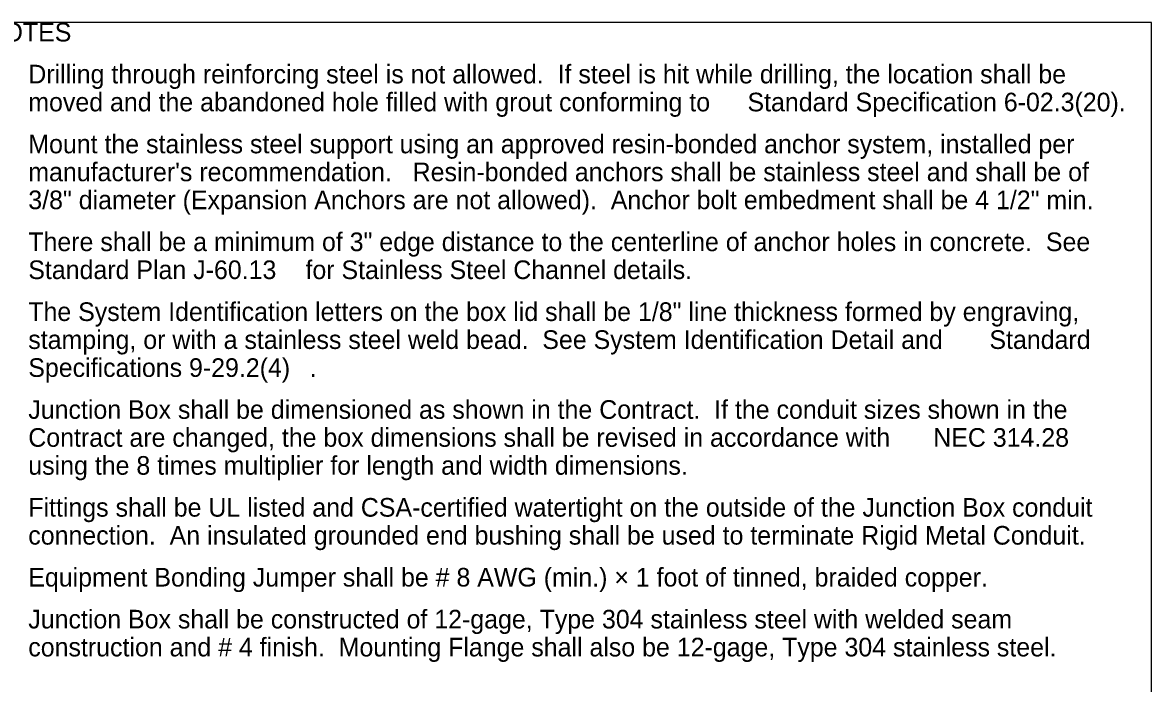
# Model space of a CAD drawing. Extents: x 99862 to 104211, y 98939 to 102076.
# Drawn here: x 101940 to 103151, y 101366 to 102076 of the extents above; entities that cross this region are included whole.
import ezdxf

# ---------------------------------------------------------------- set-up
doc = ezdxf.new("R2010")
doc.units = 0
for name, color, linetype in [('Level 1', 7, 'Continuous'), ('Level 20', 7, 'Continuous'), ('Level 60', 7, 'Continuous')]:
    doc.layers.add(name, color=color, linetype=linetype)

msp = doc.modelspace()

# ---------------------------------------------------------------- linework, layer by layer
at = {"layer": 'Level 1'}
msp.add_lwpolyline([(99862, 99999.5), (103151, 99999.5), (103151, 102075.5), (99862, 102075.5)], close=True, dxfattribs=at)
at = {"layer": 'Level 60'}
msp.add_line((103151, 102075.5), (103151, 102075.5), dxfattribs=at)

# ---------------------------------------------------------------- texts
at = {"layer": 'Level 20'}
for s, p in [('NOTES', (101900.1, 102055.3)), ('Drilling through reinforcing steel is not allowed.  If steel is hit while drilling, the location shall be ', (101946, 102010.3)), ('moved and the abandoned hole filled with grout conforming to ', (101946, 101980.3)), ('Standard Specification 6-02.3(20).  ', (102717.6, 101980.3)), ('Mount the stainless steel support using an approved resin-bonded anchor system, installed per ', (101946, 101935.3)), ("manufacturer's recommendation.   Resin-bonded anchors shall be stainless steel and shall be of ", (101946, 101905.3)), ('3/8" diameter (Expansion Anchors are not allowed).  Anchor bolt embedment shall be 4 1/2" min.  ', (101946, 101875.3)), ('There shall be a minimum of 3" edge distance to the centerline of anchor holes in concrete.  See ', (101946, 101830.3)), ('Standard Plan J-60.13 ', (101946, 101800.3)), ('for Stainless Steel Channel details.', (102243.4, 101800.3)), ('The System Identification letters on the box lid shall be 1/8" line thickness formed by engraving, ', (101946, 101755.3)), ('stamping, or with a stainless steel weld bead.  See System Identification Detail and ', (101946, 101725.3)), ('Standard ', (102977.2, 101725.3)), ('Specifications 9-29.2(4)', (101946, 101695.3)), ('.', (102247.9, 101695.3)), ('Junction Box shall be dimensioned as shown in the Contract.  If the conduit sizes shown in the ', (101946, 101650.3)), ('Contract are changed, the box dimensions shall be revised in accordance with ', (101946, 101620.3)), ('NEC 314.28 ', (102916.9, 101620.3)), ('using the 8 times multiplier for length and width dimensions.', (101946, 101590.3)), ('Fittings shall be UL listed and CSA-certified watertight on the outside of the Junction Box conduit ', (101946, 101545.3)), ('connection.  An insulated grounded end bushing shall be used to terminate Rigid Metal Conduit.', (101946, 101515.3)), ('Equipment Bonding Jumper shall be # 8 AWG (min.) × 1 foot of tinned, braided copper.', (101946, 101470.3)), ('Junction Box shall be constructed of 12-gage, Type 304 stainless steel with welded seam', (101946, 101425.3)), ('construction and # 4 finish.  Mounting Flange shall also be 12-gage, Type 304 stainless steel.  ', (101946, 101395.3))]:
    msp.add_text(s, height=20, dxfattribs=at).set_placement(p)

doc.saveas('drawing.dxf')
